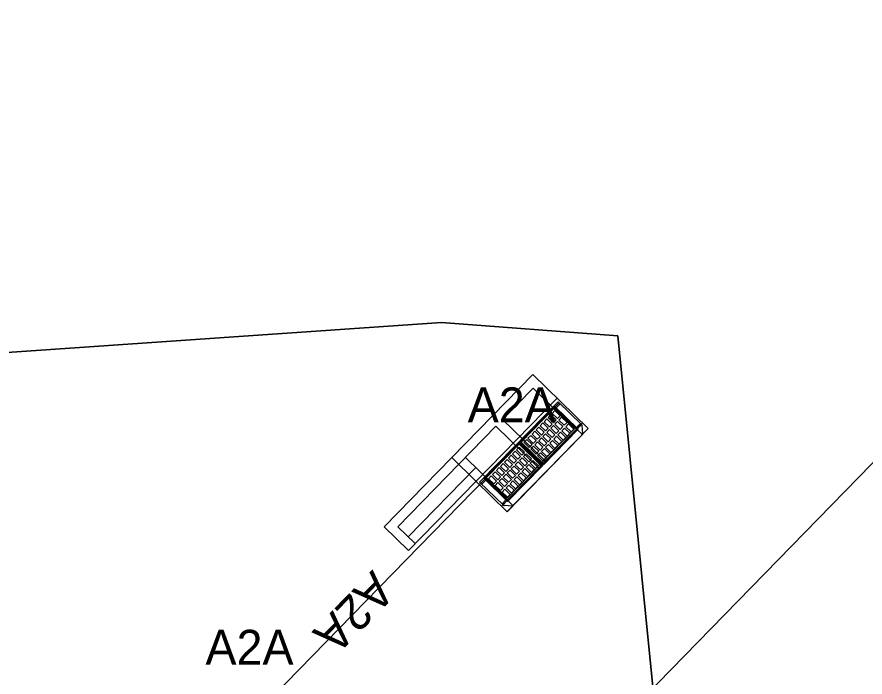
# Model space of a CAD drawing. Extents: x 2252703 to 2264864, y 13787568 to 13790989.
# Drawn here: x 2254857.99 to 2254901.78, y 13790782.84 to 13790816.93 of the extents above; entities that cross this region are included whole.
import ezdxf

# ---------------------------------------------------------------- set-up
doc = ezdxf.new("R2010")
doc.units = 0
for name, color, linetype in [('D_BOXES_1', 7, 'Continuous'), ('D_DRAIN_MISC', 7, 'Continuous'), ('D_DRAIN_NOTES_1', 7, 'Continuous'), ('D_DRN_AREA_X', 7, 'Continuous'), ('D_INLET_1', 7, 'Continuous'), ('D_PIPES_1', 7, 'Continuous')]:
    doc.layers.add(name, color=color, linetype=linetype)

msp = doc.modelspace()

# ---------------------------------------------------------------- linework, layer by layer
at = {"layer": 'D_BOXES_1'}
msp.add_line((2254879.145, 13790770.287), (2254992.252, 13790886.265), dxfattribs=at)
at = {"layer": 'D_DRAIN_MISC'}
for p, q in [((2254885.709, 13790796.711), (2254885.709, 13790796.711)), ((2254882.89, 13790795.969), (2254882.89, 13790795.969)), ((2254883.785, 13790795.096), (2254883.785, 13790795.096)), ((2254885.037, 13790793.874), (2254885.037, 13790793.874)), ((2254882.218, 13790793.131), (2254882.218, 13790793.131))]:
    msp.add_line(p, q, dxfattribs=at)
at = {"layer": 'D_DRN_AREA_X'}
for p, q in [((2254833.004, 13790797.917), (2254879.904, 13790801.143)), ((2254879.904, 13790801.143), (2254833.004, 13790797.917)), ((2254879.904, 13790801.143), (2254889.021, 13790800.465)), ((2254889.021, 13790800.465), (2254879.904, 13790801.143)), ((2254889.021, 13790800.465), (2254891.998, 13790770.575)), ((2254891.998, 13790770.575), (2254889.021, 13790800.465))]:
    msp.add_line(p, q, dxfattribs=at)
at = {"layer": 'D_INLET_1'}
for p, q in [((2254884.626, 13790798.465), (2254876.946, 13790790.59)), ((2254887.49, 13790795.673), (2254884.626, 13790798.465)), ((2254884.635, 13790797.758), (2254883.064, 13790796.148)), ((2254886.783, 13790795.664), (2254884.635, 13790797.758)), ((2254885.879, 13790797.244), (2254878.199, 13790789.369)), ((2254885.927, 13790797.057), (2254882.836, 13790793.887)), ((2254885.783, 13790796.79), (2254885.987, 13790796.999)), ((2254887.157, 13790795.858), (2254885.927, 13790797.057)), ((2254885.749, 13790796.823), (2254883.943, 13790794.971)), ((2254885.754, 13790796.76), (2254884.006, 13790794.968)), ((2254885.752, 13790796.741), (2254884.025, 13790794.97)), ((2254885.763, 13790796.599), (2254885.621, 13790796.453)), ((2254886.967, 13790795.636), (2254885.749, 13790796.823)), ((2254886.884, 13790795.636), (2254885.752, 13790796.741)), ((2254886.903, 13790795.639), (2254885.754, 13790796.76)), ((2254886.037, 13790796.331), (2254885.763, 13790796.599)), ((2254885.834, 13790796.74), (2254886.038, 13790796.949)), ((2254883.064, 13790796.148), (2254885.269, 13790793.997)), ((2254885.347, 13790796.173), (2254885.205, 13790796.027)), ((2254885.347, 13790796.173), (2254885.622, 13790795.905)), ((2254885.555, 13790796.386), (2254885.413, 13790796.24)), ((2254885.413, 13790796.24), (2254885.688, 13790795.972)), ((2254885.555, 13790796.386), (2254885.83, 13790796.118)), ((2254885.621, 13790796.453), (2254885.895, 13790796.185)), ((2254885.688, 13790795.972), (2254885.83, 13790796.118)), ((2254885.895, 13790796.185), (2254886.037, 13790796.331)), ((2254885.972, 13790796.11), (2254886.114, 13790796.256)), ((2254885.972, 13790796.11), (2254886.249, 13790795.841)), ((2254886.391, 13790795.986), (2254886.114, 13790796.256)), ((2254882.715, 13790795.79), (2254877.653, 13790790.599)), ((2254882.715, 13790795.79), (2254884.92, 13790793.639)), ((2254887.189, 13790795.966), (2254883, 13790791.67)), ((2254887.487, 13790795.675), (2254883.298, 13790791.38)), ((2254887.49, 13790795.673), (2254883.301, 13790791.377)), ((2254884.932, 13790795.747), (2254884.79, 13790795.602)), ((2254884.932, 13790795.747), (2254885.207, 13790795.479)), ((2254885.14, 13790795.96), (2254884.998, 13790795.814)), ((2254884.998, 13790795.814), (2254885.272, 13790795.547)), ((2254885.14, 13790795.96), (2254885.414, 13790795.692)), ((2254885.205, 13790796.027), (2254885.48, 13790795.759)), ((2254885.272, 13790795.547), (2254885.414, 13790795.692)), ((2254885.48, 13790795.759), (2254885.622, 13790795.905)), ((2254885.557, 13790795.685), (2254885.699, 13790795.83)), ((2254885.557, 13790795.685), (2254885.833, 13790795.415)), ((2254885.699, 13790795.83), (2254885.975, 13790795.561)), ((2254885.764, 13790795.898), (2254885.906, 13790796.043)), ((2254885.764, 13790795.898), (2254886.041, 13790795.628)), ((2254885.906, 13790796.043), (2254886.183, 13790795.773)), ((2254886.041, 13790795.628), (2254886.183, 13790795.773)), ((2254886.118, 13790795.553), (2254886.26, 13790795.699)), ((2254886.249, 13790795.841), (2254886.391, 13790795.986)), ((2254886.26, 13790795.699), (2254886.534, 13790795.431)), ((2254886.325, 13790795.766), (2254886.467, 13790795.912)), ((2254886.325, 13790795.766), (2254886.6, 13790795.498)), ((2254886.742, 13790795.644), (2254886.467, 13790795.912)), ((2254886.881, 13790795.719), (2254887.085, 13790795.928)), ((2254886.933, 13790795.669), (2254887.137, 13790795.878)), ((2254887.212, 13790795.414), (2254887.172, 13790795.827)), ((2254886.783, 13790795.664), (2254883.292, 13790792.084)), ((2254887.201, 13790795.382), (2254883.584, 13790791.673)), ((2254884.517, 13790795.321), (2254884.375, 13790795.176)), ((2254884.517, 13790795.321), (2254884.792, 13790795.054)), ((2254884.725, 13790795.534), (2254884.583, 13790795.389)), ((2254884.583, 13790795.389), (2254884.857, 13790795.121)), ((2254884.725, 13790795.534), (2254884.999, 13790795.267)), ((2254884.79, 13790795.602), (2254885.065, 13790795.334)), ((2254884.857, 13790795.121), (2254884.999, 13790795.267)), ((2254885.065, 13790795.334), (2254885.207, 13790795.479)), ((2254885.141, 13790795.259), (2254885.283, 13790795.405)), ((2254885.141, 13790795.259), (2254885.418, 13790794.989)), ((2254886.903, 13790795.639), (2254885.155, 13790793.847)), ((2254885.158, 13790793.866), (2254886.884, 13790795.636)), ((2254886.967, 13790795.636), (2254885.16, 13790793.783)), ((2254885.283, 13790795.405), (2254885.56, 13790795.135)), ((2254886.872, 13790795.583), (2254885.298, 13790793.969)), ((2254885.349, 13790795.472), (2254885.491, 13790795.618)), ((2254885.349, 13790795.472), (2254885.626, 13790795.202)), ((2254885.491, 13790795.618), (2254885.768, 13790795.348)), ((2254885.626, 13790795.202), (2254885.768, 13790795.348)), ((2254885.702, 13790795.127), (2254885.844, 13790795.273)), ((2254885.833, 13790795.415), (2254885.975, 13790795.561)), ((2254885.844, 13790795.273), (2254886.119, 13790795.005)), ((2254885.91, 13790795.34), (2254886.052, 13790795.486)), ((2254885.91, 13790795.34), (2254886.185, 13790795.072)), ((2254886.052, 13790795.486), (2254886.327, 13790795.218)), ((2254886.118, 13790795.553), (2254886.392, 13790795.285)), ((2254886.392, 13790795.285), (2254886.534, 13790795.431)), ((2254886.6, 13790795.498), (2254886.742, 13790795.644)), ((2254886.937, 13790795.606), (2254887.184, 13790795.365)), ((2254882.107, 13790793.089), (2254883.913, 13790794.941)), ((2254882.17, 13790793.085), (2254883.918, 13790794.878)), ((2254882.19, 13790793.088), (2254883.916, 13790794.858)), ((2254885.131, 13790793.754), (2254883.913, 13790794.941)), ((2254885.048, 13790793.754), (2254883.916, 13790794.858)), ((2254885.068, 13790793.757), (2254883.918, 13790794.878)), ((2254885.16, 13790793.783), (2254883.943, 13790794.971)), ((2254885.155, 13790793.847), (2254884.006, 13790794.968)), ((2254885.158, 13790793.866), (2254884.025, 13790794.97)), ((2254884.309, 13790795.109), (2254884.167, 13790794.963)), ((2254884.442, 13790794.695), (2254884.167, 13790794.963)), ((2254884.309, 13790795.109), (2254884.584, 13790794.841)), ((2254884.375, 13790795.176), (2254884.65, 13790794.908)), ((2254884.442, 13790794.695), (2254884.584, 13790794.841)), ((2254884.65, 13790794.908), (2254884.792, 13790795.054)), ((2254884.726, 13790794.833), (2254884.868, 13790794.979)), ((2254884.726, 13790794.833), (2254885.003, 13790794.563)), ((2254884.868, 13790794.979), (2254885.145, 13790794.709)), ((2254884.934, 13790795.046), (2254885.076, 13790795.192)), ((2254884.934, 13790795.046), (2254885.21, 13790794.776)), ((2254885.076, 13790795.192), (2254885.353, 13790794.922)), ((2254885.21, 13790794.776), (2254885.353, 13790794.922)), ((2254885.287, 13790794.702), (2254885.429, 13790794.847)), ((2254885.418, 13790794.989), (2254885.56, 13790795.135)), ((2254885.429, 13790794.847), (2254885.704, 13790794.579)), ((2254885.495, 13790794.914), (2254885.637, 13790795.06)), ((2254885.495, 13790794.914), (2254885.769, 13790794.647)), ((2254885.637, 13790795.06), (2254885.911, 13790794.792)), ((2254885.702, 13790795.127), (2254885.977, 13790794.859)), ((2254885.769, 13790794.647), (2254885.911, 13790794.792)), ((2254885.977, 13790794.859), (2254886.119, 13790795.005)), ((2254886.185, 13790795.072), (2254886.327, 13790795.218)), ((2254883.577, 13790794.358), (2254883.719, 13790794.504)), ((2254883.577, 13790794.358), (2254883.852, 13790794.09)), ((2254883.719, 13790794.504), (2254883.994, 13790794.236)), ((2254883.785, 13790794.571), (2254883.927, 13790794.716)), ((2254883.785, 13790794.571), (2254884.06, 13790794.303)), ((2254884.202, 13790794.449), (2254883.927, 13790794.716)), ((2254884.202, 13790794.449), (2254884.06, 13790794.303)), ((2254884.278, 13790794.374), (2254884.136, 13790794.228)), ((2254884.555, 13790794.104), (2254884.278, 13790794.374)), ((2254884.519, 13790794.62), (2254884.661, 13790794.766)), ((2254884.795, 13790794.351), (2254884.519, 13790794.62)), ((2254884.661, 13790794.766), (2254884.937, 13790794.496)), ((2254884.795, 13790794.351), (2254884.937, 13790794.496)), ((2254884.872, 13790794.276), (2254885.014, 13790794.421)), ((2254885.003, 13790794.563), (2254885.145, 13790794.709)), ((2254885.014, 13790794.421), (2254885.289, 13790794.154)), ((2254885.08, 13790794.489), (2254885.222, 13790794.634)), ((2254885.08, 13790794.489), (2254885.354, 13790794.221)), ((2254885.222, 13790794.634), (2254885.496, 13790794.367)), ((2254885.287, 13790794.702), (2254885.562, 13790794.434)), ((2254885.354, 13790794.221), (2254885.496, 13790794.367)), ((2254885.562, 13790794.434), (2254885.704, 13790794.579)), ((2254881.69, 13790792.948), (2254880.437, 13790794.17)), ((2254883.292, 13790792.084), (2254881.144, 13790794.179)), ((2254883.162, 13790793.932), (2254883.304, 13790794.078)), ((2254883.162, 13790793.932), (2254883.437, 13790793.664)), ((2254883.304, 13790794.078), (2254883.579, 13790793.81)), ((2254883.37, 13790794.145), (2254883.512, 13790794.291)), ((2254883.37, 13790794.145), (2254883.644, 13790793.877)), ((2254883.512, 13790794.291), (2254883.786, 13790794.023)), ((2254883.786, 13790794.023), (2254883.644, 13790793.877)), ((2254883.863, 13790793.948), (2254883.721, 13790793.803)), ((2254883.994, 13790794.236), (2254883.852, 13790794.09)), ((2254883.863, 13790793.948), (2254884.14, 13790793.678)), ((2254884.071, 13790794.161), (2254883.929, 13790794.015)), ((2254883.929, 13790794.015), (2254884.205, 13790793.746)), ((2254884.071, 13790794.161), (2254884.347, 13790793.891)), ((2254884.136, 13790794.228), (2254884.413, 13790793.958)), ((2254884.555, 13790794.104), (2254884.413, 13790793.958)), ((2254884.632, 13790794.029), (2254884.49, 13790793.884)), ((2254884.906, 13790793.762), (2254884.632, 13790794.029)), ((2254885.147, 13790794.008), (2254884.872, 13790794.276)), ((2254885.147, 13790794.008), (2254885.289, 13790794.154)), ((2254881.681, 13790793.655), (2254878.19, 13790790.076)), ((2254882.836, 13790793.887), (2254881.877, 13790792.904)), ((2254882.747, 13790793.506), (2254882.889, 13790793.652)), ((2254882.747, 13790793.506), (2254883.022, 13790793.239)), ((2254882.889, 13790793.652), (2254883.164, 13790793.384)), ((2254882.955, 13790793.719), (2254883.097, 13790793.865)), ((2254882.955, 13790793.719), (2254883.229, 13790793.452)), ((2254883.097, 13790793.865), (2254883.371, 13790793.597)), ((2254883.371, 13790793.597), (2254883.229, 13790793.452)), ((2254883.448, 13790793.522), (2254883.306, 13790793.377)), ((2254883.32, 13790791.964), (2254885.068, 13790793.757)), ((2254885.048, 13790793.754), (2254883.322, 13790791.984)), ((2254883.324, 13790791.901), (2254885.131, 13790793.754)), ((2254884.949, 13790793.611), (2254883.375, 13790791.998)), ((2254883.579, 13790793.81), (2254883.437, 13790793.664)), ((2254883.448, 13790793.522), (2254883.725, 13790793.253)), ((2254883.655, 13790793.735), (2254883.513, 13790793.59)), ((2254883.513, 13790793.59), (2254883.79, 13790793.32)), ((2254883.655, 13790793.735), (2254883.932, 13790793.465)), ((2254883.721, 13790793.803), (2254883.998, 13790793.533)), ((2254884.14, 13790793.678), (2254883.998, 13790793.533)), ((2254884.216, 13790793.604), (2254884.074, 13790793.458)), ((2254884.347, 13790793.891), (2254884.205, 13790793.746)), ((2254884.216, 13790793.604), (2254884.491, 13790793.336)), ((2254884.424, 13790793.816), (2254884.282, 13790793.671)), ((2254884.282, 13790793.671), (2254884.557, 13790793.403)), ((2254884.424, 13790793.816), (2254884.699, 13790793.549)), ((2254884.49, 13790793.884), (2254884.764, 13790793.616)), ((2254884.699, 13790793.549), (2254884.557, 13790793.403)), ((2254884.906, 13790793.762), (2254884.764, 13790793.616)), ((2254882.141, 13790793.055), (2254881.937, 13790792.846)), ((2254883.324, 13790791.901), (2254882.107, 13790793.089)), ((2254883.32, 13790791.964), (2254882.17, 13790793.085)), ((2254883.322, 13790791.984), (2254882.19, 13790793.088)), ((2254882.332, 13790793.081), (2254882.474, 13790793.226)), ((2254882.606, 13790792.813), (2254882.332, 13790793.081)), ((2254882.474, 13790793.226), (2254882.748, 13790792.959)), ((2254882.539, 13790793.294), (2254882.681, 13790793.439)), ((2254882.539, 13790793.294), (2254882.814, 13790793.026)), ((2254882.681, 13790793.439), (2254882.956, 13790793.171)), ((2254882.956, 13790793.171), (2254882.814, 13790793.026)), ((2254883.033, 13790793.097), (2254882.891, 13790792.951)), ((2254883.164, 13790793.384), (2254883.022, 13790793.239)), ((2254883.033, 13790793.097), (2254883.309, 13790792.827)), ((2254883.24, 13790793.31), (2254883.098, 13790793.164)), ((2254883.098, 13790793.164), (2254883.375, 13790792.894)), ((2254883.24, 13790793.31), (2254883.517, 13790793.04)), ((2254883.306, 13790793.377), (2254883.582, 13790793.107)), ((2254883.517, 13790793.04), (2254883.375, 13790792.894)), ((2254883.725, 13790793.253), (2254883.582, 13790793.107)), ((2254883.801, 13790793.178), (2254883.659, 13790793.032)), ((2254883.932, 13790793.465), (2254883.79, 13790793.32)), ((2254883.801, 13790793.178), (2254884.076, 13790792.91)), ((2254884.009, 13790793.391), (2254883.867, 13790793.245)), ((2254883.867, 13790793.245), (2254884.141, 13790792.977)), ((2254884.009, 13790793.391), (2254884.283, 13790793.123)), ((2254884.074, 13790793.458), (2254884.349, 13790793.19)), ((2254884.283, 13790793.123), (2254884.141, 13790792.977)), ((2254884.491, 13790793.336), (2254884.349, 13790793.19)), ((2254883.301, 13790791.377), (2254881.69, 13790792.948)), ((2254883.107, 13790791.706), (2254881.877, 13790792.904)), ((2254882.192, 13790793.006), (2254881.988, 13790792.797)), ((2254882.748, 13790792.959), (2254882.606, 13790792.813)), ((2254882.825, 13790792.884), (2254882.683, 13790792.738)), ((2254882.96, 13790792.468), (2254882.683, 13790792.738)), ((2254882.825, 13790792.884), (2254883.102, 13790792.614)), ((2254882.891, 13790792.951), (2254883.167, 13790792.681)), ((2254883.102, 13790792.614), (2254882.96, 13790792.468)), ((2254883.309, 13790792.827), (2254883.167, 13790792.681)), ((2254883.386, 13790792.752), (2254883.244, 13790792.606)), ((2254883.244, 13790792.606), (2254883.519, 13790792.339)), ((2254883.386, 13790792.752), (2254883.661, 13790792.484)), ((2254883.594, 13790792.965), (2254883.452, 13790792.819)), ((2254883.452, 13790792.819), (2254883.726, 13790792.552)), ((2254883.594, 13790792.965), (2254883.868, 13790792.697)), ((2254883.659, 13790793.032), (2254883.934, 13790792.764)), ((2254883.868, 13790792.697), (2254883.726, 13790792.552)), ((2254884.076, 13790792.91), (2254883.934, 13790792.764)), ((2254883.178, 13790792.539), (2254883.036, 13790792.394)), ((2254883.311, 13790792.126), (2254883.036, 13790792.394)), ((2254883.178, 13790792.539), (2254883.453, 13790792.271)), ((2254883.453, 13790792.271), (2254883.311, 13790792.126)), ((2254883.661, 13790792.484), (2254883.519, 13790792.339)), ((2254883.239, 13790791.984), (2254883.035, 13790791.775)), ((2254883.29, 13790791.934), (2254883.086, 13790791.725)), ((2254883.354, 13790791.931), (2254883.601, 13790791.69)), ((2254883.552, 13790791.662), (2254883.139, 13790791.691)), ((2254876.946, 13790790.59), (2254878.199, 13790789.369)), ((2254877.653, 13790790.599), (2254878.548, 13790789.726))]:
    msp.add_line(p, q, dxfattribs=at)
for centre, start_param, end_param in [((2254887.128, 13790795.828), 0.80294, 1.570796), ((2254887.167, 13790795.415), 0, 0.80294), ((2254883.136, 13790791.735), 4.712389, 5.480245), ((2254883.55, 13790791.706), 5.480245, 6.283185)]:
    msp.add_ellipse(centre, major_axis=(0.0341, -0.0332), ratio=0.877193, start_param=start_param, end_param=end_param, dxfattribs=at)
at = {"layer": 'D_PIPES_1'}
msp.add_line((2254882.218, 13790793.131), (2254868.254, 13790778.813), dxfattribs=at)

# ---------------------------------------------------------------- texts
at = {"layer": 'D_DRAIN_NOTES_1'}
for p in [(2254881.262, 13790795.996), (2254867.721, 13790783.476)]:
    msp.add_text('A2A', height=1.8, dxfattribs=at).set_placement(p)
msp.add_text('A2A', height=1.8, rotation=225.7179, dxfattribs=at).set_placement((2254876.353, 13790788.406))

doc.saveas('drawing.dxf')
